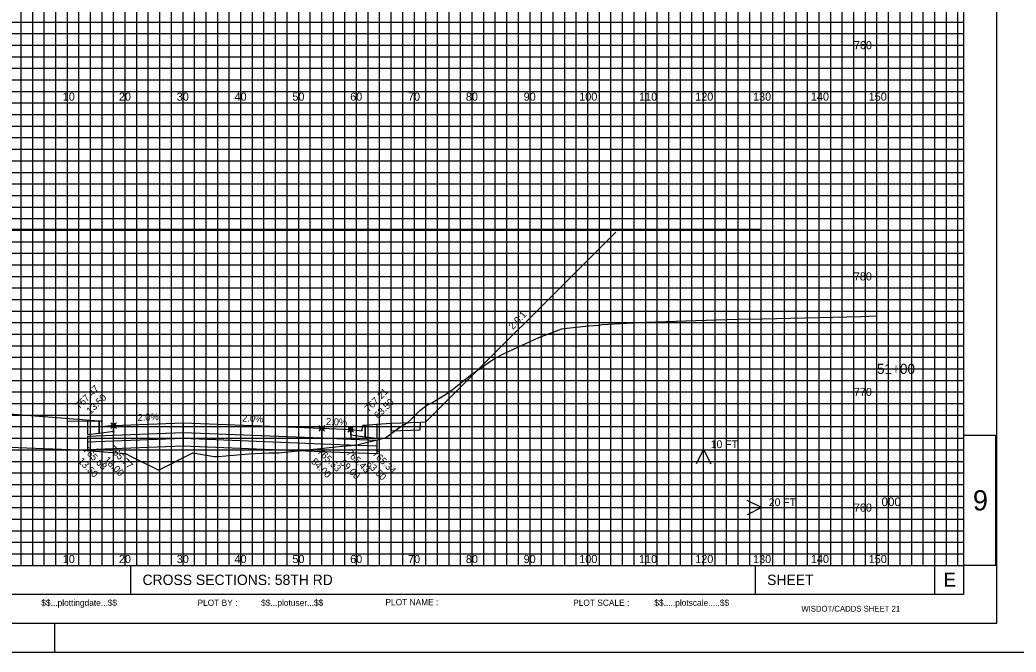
# Model space of a CAD drawing. Extents: x 578243 to 601557, y 174899 to 175559.
# Drawn here: x 601041.6 to 601213.9, y 174898.8 to 175008.2 of the extents above; entities that cross this region are included whole.
import ezdxf

# ---------------------------------------------------------------- set-up
doc = ezdxf.new("R2010")
doc.units = 0
for name, color, linetype in [('E_PROF_Grid', 7, 'Continuous'), ('E_PROF_GridMin', 7, 'Continuous'), ('P_CRDR_Label', 7, 'Continuous'), ('P_CRDR_Link', 7, 'Continuous'), ('P_E_XS_Ground', 7, 'Continuous'), ('P_RW_SlopeIntercepts', 7, 'Continuous'), ('P_XS_Text', 7, 'Continuous'), ('PLT_Sheet_Border', 7, 'Continuous'), ('PLT_Sheet_Info', 7, 'Continuous')]:
    doc.layers.add(name, color=color, linetype=linetype)

msp = doc.modelspace()

# ---------------------------------------------------------------- linework, layer by layer
at = {"layer": 'E_PROF_Grid'}
for p, q in [((601049.84, 174913.8), (601049.84, 175108.8)), ((601059.84, 174913.8), (601059.84, 175108.8)), ((601069.84, 174913.8), (601069.84, 175108.8)), ((601079.84, 174913.8), (601079.84, 175108.8)), ((601089.84, 174913.8), (601089.84, 175108.8)), ((601099.84, 174913.8), (601099.84, 175108.8)), ((601109.84, 174913.8), (601109.84, 175108.8)), ((601119.84, 174913.8), (601119.84, 175108.8)), ((601129.84, 174913.8), (601129.84, 175108.8)), ((601139.84, 174913.8), (601139.84, 175108.8)), ((601149.84, 174913.8), (601149.84, 175108.8)), ((601159.84, 174913.8), (601159.84, 175108.8)), ((601169.84, 174913.8), (601169.84, 175108.8)), ((601179.84, 174913.8), (601179.84, 175108.8)), ((601189.84, 174913.8), (601189.84, 175108.8)), ((601199.84, 174913.8), (601199.84, 175108.8)), ((600889.84, 175003.8), (601204.84, 175003.8)), ((600889.84, 174993.8), (601204.84, 174993.8)), ((600889.84, 174983.8), (601204.84, 174983.8)), ((600889.84, 174973.8), (601204.84, 174973.8)), ((600889.84, 174963.8), (601204.84, 174963.8)), ((600889.84, 174953.8), (601204.84, 174953.8)), ((600889.84, 174943.8), (601204.84, 174943.8)), ((600889.84, 174933.8), (601204.84, 174933.8)), ((600889.84, 174923.8), (601204.84, 174923.8))]:
    msp.add_line(p, q, dxfattribs=at)
at = {"layer": 'E_PROF_GridMin'}
for p, q in [((601041.84, 174913.8), (601041.84, 175108.8)), ((601043.84, 174913.8), (601043.84, 175108.8)), ((601045.84, 174913.8), (601045.84, 175108.8)), ((601047.84, 174913.8), (601047.84, 175108.8)), ((601051.84, 174913.8), (601051.84, 175108.8)), ((601053.84, 174913.8), (601053.84, 175108.8)), ((601055.84, 174913.8), (601055.84, 175108.8)), ((601057.84, 174913.8), (601057.84, 175108.8)), ((601061.84, 174913.8), (601061.84, 175108.8)), ((601063.84, 174913.8), (601063.84, 175108.8)), ((601065.84, 174913.8), (601065.84, 175108.8)), ((601067.84, 174913.8), (601067.84, 175108.8)), ((601071.84, 174913.8), (601071.84, 175108.8)), ((601073.84, 174913.8), (601073.84, 175108.8)), ((601075.84, 174913.8), (601075.84, 175108.8)), ((601077.84, 174913.8), (601077.84, 175108.8)), ((601081.84, 174913.8), (601081.84, 175108.8)), ((601083.84, 174913.8), (601083.84, 175108.8)), ((601085.84, 174913.8), (601085.84, 175108.8)), ((601087.84, 174913.8), (601087.84, 175108.8)), ((601091.84, 174913.8), (601091.84, 175108.8)), ((601093.84, 174913.8), (601093.84, 175108.8)), ((601095.84, 174913.8), (601095.84, 175108.8)), ((601097.84, 174913.8), (601097.84, 175108.8)), ((601101.84, 174913.8), (601101.84, 175108.8)), ((601103.84, 174913.8), (601103.84, 175108.8)), ((601105.84, 174913.8), (601105.84, 175108.8)), ((601107.84, 174913.8), (601107.84, 175108.8)), ((601111.84, 174913.8), (601111.84, 175108.8)), ((601113.84, 174913.8), (601113.84, 175108.8)), ((601115.84, 174913.8), (601115.84, 175108.8)), ((601117.84, 174913.8), (601117.84, 175108.8)), ((601121.84, 174913.8), (601121.84, 175108.8)), ((601123.84, 174913.8), (601123.84, 175108.8)), ((601125.84, 174913.8), (601125.84, 175108.8)), ((601127.84, 174913.8), (601127.84, 175108.8)), ((601131.84, 174913.8), (601131.84, 175108.8)), ((601133.84, 174913.8), (601133.84, 175108.8)), ((601135.84, 174913.8), (601135.84, 175108.8)), ((601137.84, 174913.8), (601137.84, 175108.8)), ((601141.84, 174913.8), (601141.84, 175108.8)), ((601143.84, 174913.8), (601143.84, 175108.8)), ((601145.84, 174913.8), (601145.84, 175108.8)), ((601147.84, 174913.8), (601147.84, 175108.8)), ((601151.84, 174913.8), (601151.84, 175108.8)), ((601153.84, 174913.8), (601153.84, 175108.8)), ((601155.84, 174913.8), (601155.84, 175108.8)), ((601157.84, 174913.8), (601157.84, 175108.8)), ((601161.84, 174913.8), (601161.84, 175108.8)), ((601163.84, 174913.8), (601163.84, 175108.8)), ((601165.84, 174913.8), (601165.84, 175108.8)), ((601167.84, 174913.8), (601167.84, 175108.8)), ((601171.84, 174913.8), (601171.84, 175108.8)), ((601173.84, 174913.8), (601173.84, 175108.8)), ((601175.84, 174913.8), (601175.84, 175108.8)), ((601177.84, 174913.8), (601177.84, 175108.8)), ((601181.84, 174913.8), (601181.84, 175108.8)), ((601183.84, 174913.8), (601183.84, 175108.8)), ((601185.84, 174913.8), (601185.84, 175108.8)), ((601187.84, 174913.8), (601187.84, 175108.8)), ((601191.84, 174913.8), (601191.84, 175108.8)), ((601193.84, 174913.8), (601193.84, 175108.8)), ((601195.84, 174913.8), (601195.84, 175108.8)), ((601197.84, 174913.8), (601197.84, 175108.8)), ((601201.84, 174913.8), (601201.84, 175108.8)), ((601203.84, 174913.8), (601203.84, 175108.8)), ((600889.84, 175007.8), (601204.84, 175007.8)), ((600889.84, 175005.8), (601204.84, 175005.8)), ((600889.84, 175001.8), (601204.84, 175001.8)), ((600889.84, 174999.8), (601204.84, 174999.8)), ((600889.84, 174997.8), (601204.84, 174997.8)), ((600889.84, 174995.8), (601204.84, 174995.8)), ((600889.84, 174991.8), (601204.84, 174991.8)), ((600889.84, 174989.8), (601204.84, 174989.8)), ((600889.84, 174987.8), (601204.84, 174987.8)), ((600889.84, 174985.8), (601204.84, 174985.8)), ((600889.84, 174981.8), (601204.84, 174981.8)), ((600889.84, 174979.8), (601204.84, 174979.8)), ((600889.84, 174977.8), (601204.84, 174977.8)), ((600889.84, 174975.8), (601204.84, 174975.8)), ((600889.84, 174971.8), (601204.84, 174971.8)), ((600889.84, 174969.8), (601204.84, 174969.8)), ((600889.84, 174967.8), (601204.84, 174967.8)), ((600889.84, 174965.8), (601204.84, 174965.8)), ((600889.84, 174961.8), (601204.84, 174961.8)), ((600889.84, 174959.8), (601204.84, 174959.8)), ((600889.84, 174957.8), (601204.84, 174957.8)), ((600889.84, 174955.8), (601204.84, 174955.8)), ((600889.84, 174951.8), (601204.84, 174951.8)), ((600889.84, 174949.8), (601204.84, 174949.8)), ((600889.84, 174947.8), (601204.84, 174947.8)), ((600889.84, 174945.8), (601204.84, 174945.8)), ((600889.84, 174941.8), (601204.84, 174941.8)), ((600889.84, 174939.8), (601204.84, 174939.8)), ((600889.84, 174937.8), (601204.84, 174937.8)), ((600889.84, 174935.8), (601204.84, 174935.8)), ((600889.84, 174931.8), (601204.84, 174931.8)), ((600889.84, 174929.8), (601204.84, 174929.8)), ((600889.84, 174927.8), (601204.84, 174927.8)), ((600889.84, 174925.8), (601204.84, 174925.8)), ((600889.84, 174921.8), (601204.84, 174921.8)), ((600889.84, 174919.8), (601204.84, 174919.8)), ((600889.84, 174917.8), (601204.84, 174917.8)), ((600889.84, 174915.8), (601204.84, 174915.8)), ((601207.19, 174898.8), (601217.19, 174898.8))]:
    msp.add_line(p, q, dxfattribs=at)
at = {"layer": 'P_CRDR_Label'}
for points in [[(601057.34, 174937.5), (601058.33, 174938.49)], [(601057.34, 174938.49), (601058.33, 174937.5)], [(601093.34, 174937.02), (601094.33, 174938.01)], [(601093.34, 174938.01), (601094.33, 174937.02)], [(601098.34, 174936.82), (601099.33, 174937.81)], [(601098.34, 174937.81), (601099.33, 174936.82)]]:
    msp.add_lwpolyline(points, dxfattribs=at)
for centre in [(601057.84, 174938), (601093.84, 174937.52), (601098.84, 174937.32)]:
    msp.add_circle(centre, 0.35, dxfattribs=at)
at = {"layer": 'P_CRDR_Link'}
msp.add_line((601144.69, 174971.46), (601111.84, 174938.61), dxfattribs=at)
for points in [[(601055.34, 174938.75), (601039.84, 174939.99)], [(601055.34, 174938.75), (601039.84, 174939.99)], [(601053.34, 174938.73), (601049.84, 174938.7)], [(601053.34, 174938.73), (601049.84, 174938.7)], [(601055.34, 174938.75), (601053.34, 174938.73)], [(601053.34, 174938.73), (601053.34, 174936.43)], [(601053.34, 174938.73), (601053.34, 174936.43)], [(601053.34, 174938.73), (601053.34, 174936.43)], [(601055.66, 174938.75), (601055.34, 174938.75)], [(601055.66, 174938.75), (601055.34, 174938.75)], [(601055.34, 174938.75), (601055.34, 174936.68)], [(601055.34, 174936.68), (601055.34, 174938.75)], [(601055.74, 174938.7), (601055.66, 174938.75)], [(601055.74, 174938.7), (601055.66, 174938.75)], [(601055.8, 174938.59), (601055.74, 174938.7)], [(601055.8, 174938.59), (601055.74, 174938.7)], [(601055.83, 174938.43), (601055.8, 174938.59)], [(601055.83, 174938.43), (601055.8, 174938.59)], [(601055.84, 174937.75), (601055.83, 174938.43)], [(601055.84, 174937.75), (601055.83, 174938.43)], [(601057.84, 174938), (601069.84, 174938.48)], [(601069.84, 174938.48), (601069.84, 174936.81)], [(601069.84, 174938.48), (601093.84, 174937.52)], [(601069.84, 174938.48), (601069.84, 174936.81)], [(601101.34, 174938.07), (601103.34, 174938.23)], [(601103.34, 174938.23), (601105.84, 174938.43)], [(601103.34, 174938.23), (601105.84, 174938.43)], [(601103.34, 174938.23), (601103.34, 174935.75)], [(601103.34, 174938.23), (601103.34, 174935.75)], [(601103.34, 174938.23), (601103.34, 174935.75)], [(601105.84, 174938.43), (601110.84, 174938.58)], [(601105.84, 174938.43), (601110.84, 174938.58)], [(601105.84, 174938.43), (601105.84, 174937.76)], [(601110.84, 174938.58), (601110.83, 174937.91)], [(601110.84, 174938.58), (601111.84, 174938.61)], [(601110.84, 174938.58), (601111.84, 174938.61)], [(601053.34, 174936.43), (601055.34, 174936.68)], [(601055.34, 174936.68), (601057.84, 174937)], [(601055.34, 174936.68), (601057.84, 174937)], [(601057.84, 174938), (601055.84, 174937.75)], [(601057.84, 174938), (601055.84, 174937.75)], [(601057.84, 174937), (601057.84, 174938)], [(601057.84, 174938), (601057.84, 174936.33)], [(601057.84, 174936.33), (601069.84, 174936.81)], [(601069.84, 174936.81), (601069.84, 174935.81)], [(601069.84, 174936.81), (601093.84, 174935.85)], [(601069.84, 174936.81), (601069.84, 174935.81)], [(601093.84, 174937.52), (601093.84, 174935.85)], [(601093.84, 174937.52), (601098.84, 174937.32)], [(601093.84, 174937.52), (601093.84, 174935.85)], [(601098.84, 174937.32), (601098.84, 174935.65)], [(601098.84, 174937.32), (601100.84, 174937.07)], [(601098.84, 174937.32), (601100.84, 174937.07)], [(601098.84, 174936.32), (601098.84, 174937.32)], [(601100.84, 174937.07), (601100.85, 174937.75)], [(601100.84, 174937.07), (601100.85, 174937.75)], [(601100.85, 174937.75), (601100.88, 174937.91)], [(601100.85, 174937.75), (601100.88, 174937.91)], [(601100.88, 174937.91), (601100.94, 174938.02)], [(601100.88, 174937.91), (601100.94, 174938.02)], [(601100.94, 174938.02), (601101.02, 174938.07)], [(601100.94, 174938.02), (601101.02, 174938.07)], [(601101.02, 174938.07), (601101.34, 174938.07)], [(601101.02, 174938.07), (601101.34, 174938.07)], [(601101.34, 174938.07), (601101.34, 174936)], [(601101.34, 174936), (601101.34, 174938.07)], [(601105.84, 174937.76), (601110.83, 174937.91)], [(601105.84, 174937.76), (601105.85, 174937.1)], [(601105.85, 174937.1), (601110.83, 174937.25)], [(601110.83, 174937.25), (601110.83, 174937.91)], [(601053.34, 174936.15), (601057.84, 174936.33)], [(601053.34, 174936.15), (601053.34, 174935.15)], [(601053.34, 174935.15), (601069.84, 174935.81)], [(601053.34, 174935.15), (601053.34, 174933.82)], [(601069.84, 174935.81), (601069.84, 174934.48)], [(601069.84, 174935.81), (601093.84, 174934.85)], [(601069.84, 174935.81), (601069.84, 174934.48)], [(601093.84, 174935.85), (601093.84, 174934.85)], [(601093.84, 174935.85), (601098.84, 174935.65)], [(601093.84, 174935.85), (601093.84, 174934.85)], [(601093.84, 174934.85), (601093.84, 174933.52)], [(601093.84, 174934.85), (601103.34, 174934.47)], [(601093.84, 174934.85), (601093.84, 174933.52)], [(601101.34, 174936), (601098.84, 174936.32)], [(601101.34, 174936), (601098.84, 174936.32)], [(601098.84, 174935.65), (601103.34, 174935.47)], [(601103.34, 174935.75), (601101.34, 174936)], [(601103.34, 174935.47), (601103.34, 174934.47)], [(601053.34, 174933.82), (601069.84, 174934.48)], [(601069.84, 174934.48), (601093.84, 174933.52)], [(601093.84, 174933.52), (601103.34, 174933.14)], [(601103.34, 174934.47), (601103.34, 174933.14)]]:
    msp.add_lwpolyline(points, dxfattribs=at)
at = {"layer": 'P_E_XS_Ground'}
msp.add_lwpolyline([(601039.84, 174934.26), (601051.84, 174933.78), (601056.9, 174933.37), (601059.9, 174933.13), (601061.19, 174932.48), (601065.54, 174930.31), (601065.58, 174930.3), (601071.52, 174933.27), (601075.2, 174932.62), (601075.89, 174932.61), (601081.24, 174933.12), (601084.67, 174933.26), (601085.88, 174933.3), (601086.42, 174933.29), (601091.83, 174933.83), (601093.64, 174934.03), (601096.19, 174934.32), (601097.42, 174934.42), (601099.69, 174934.58), (601099.91, 174934.63), (601099.91, 174934.63), (601104.81, 174935.85), (601104.84, 174935.86), (601107.33, 174937.74), (601108.78, 174938.59), (601110.78, 174940.59), (601112, 174941.49), (601112.86, 174941.95), (601115.84, 174943.79), (601117.88, 174945.36), (601119.79, 174946.87), (601122.6, 174948.83), (601123.69, 174949.57), (601125.36, 174950.43), (601131.37, 174953.24), (601135.35, 174954.71), (601135.68, 174954.8), (601140.03, 174955.23), (601141.84, 174955.38), (601142.32, 174955.46), (601149.79, 174955.9), (601162.05, 174956.29), (601165.86, 174956.4), (601170.07, 174956.47), (601187.07, 174956.87), (601189.84, 174956.96)], dxfattribs=at)
at = {"layer": 'P_RW_SlopeIntercepts'}
msp.add_line((600933.84, 174971.98), (601169.84, 174971.98), dxfattribs=at)
at = {"layer": 'PLT_Sheet_Border'}
for points in [[(600877.19, 174898.8), (601217.19, 174898.8), (601217.19, 175118.8), (600877.19, 175118.8)], [(600879.59, 174903.8), (601210.59, 174903.8), (601210.59, 175113.8), (600879.59, 175113.8)]]:
    msp.add_lwpolyline(points, close=True, dxfattribs=at)
at = {"layer": 'PLT_Sheet_Info'}
for p, q in [((601204.84, 174908.8), (601204.84, 175108.8)), ((600889.84, 174913.8), (601204.84, 174913.8)), ((601060.84, 174908.8), (601060.84, 174913.8)), ((601168.84, 174908.8), (601168.84, 174913.8)), ((601199.84, 174908.8), (601199.84, 174913.8)), ((600889.84, 174908.8), (601204.84, 174908.8)), ((601047.69, 174898.8), (601047.69, 174903.8)), ((601042.69, 174898.8), (601052.69, 174898.8))]:
    msp.add_line(p, q, dxfattribs=at)
msp.add_lwpolyline([(601204.84, 174936.3), (601210.34, 174936.3), (601210.34, 174913.8), (601204.84, 174913.8)], close=True, dxfattribs=at)
for points in [[(601159.84, 174933.84), (601158.6, 174931.36)], [(601159.84, 174923.8), (601159.84, 174933.84), (601161.08, 174931.36)], [(601169.89, 174923.8), (601167.4, 174925.04)], [(601159.84, 174923.8), (601169.89, 174923.8), (601167.4, 174922.55)]]:
    msp.add_lwpolyline(points, dxfattribs=at)

# ---------------------------------------------------------------- texts
at = {"layer": 'P_CRDR_Label'}
for s, rotation, p in [('2.0:1', 46.711, (601126.88, 174954.52)), ('767.47', 45, (601051.93, 174940.77)), ('13.50', 45, (601053.87, 174939.89)), ('767.21', 45, (601101.93, 174940.27)), ('63.50', 45, (601103.58, 174939.1)), ('2.0%', 2.2906, (601062, 174938.78)), ('2.0%', 357.7094, (601080.05, 174938.69)), ('2.0%', 357.7094, (601094.55, 174938.11)), ('765.68', 315, (601052.49, 174933.67)), ('765.77', 315, (601056.99, 174933.85)), ('765.53', 315, (601092.99, 174933.37)), ('765.43', 315, (601097.99, 174933.17)), ('765.34', 315, (601102.49, 174932.99)), ('13.50', 315, (601051.6, 174931.73)), ('18.00', 315, (601056.08, 174931.94)), ('54.00', 315, (601091.9, 174931.64)), ('59.00', 315, (601096.89, 174931.44)), ('63.50', 315, (601101.43, 174931.23))]:
    msp.add_text(s, height=1.2, rotation=rotation, dxfattribs=at).set_placement(p)
at = {"layer": 'P_XS_Text'}
for s, height, p in [('760', 1.4, (601185.84, 175003.1)), ('10', 1.4, (601049.04, 174994.2)), ('20', 1.4, (601058.75, 174994.2)), ('30', 1.4, (601068.75, 174994.2)), ('40', 1.4, (601078.75, 174994.2)), ('50', 1.4, (601088.75, 174994.2)), ('60', 1.4, (601098.75, 174994.2)), ('70', 1.4, (601108.75, 174994.2)), ('80', 1.4, (601118.75, 174994.2)), ('90', 1.4, (601128.74, 174994.2)), ('100', 1.4, (601138.36, 174994.2)), ('110', 1.4, (601148.7, 174994.2)), ('120', 1.4, (601158.41, 174994.2)), ('130', 1.4, (601168.41, 174994.2)), ('140', 1.4, (601178.41, 174994.2)), ('150', 1.4, (601188.41, 174994.2)), ('780', 1.4, (601185.84, 174963.1)), ('51+00', 1.75, (601189.84, 174946.92)), ('770', 1.4, (601185.84, 174943.1)), ('760', 1.4, (601185.84, 174923.1)), ('10', 1.4, (601049.04, 174914.2)), ('20', 1.4, (601058.75, 174914.2)), ('30', 1.4, (601068.75, 174914.2)), ('40', 1.4, (601078.75, 174914.2)), ('50', 1.4, (601088.75, 174914.2)), ('60', 1.4, (601098.75, 174914.2)), ('70', 1.4, (601108.75, 174914.2)), ('80', 1.4, (601118.75, 174914.2)), ('90', 1.4, (601128.74, 174914.2)), ('100', 1.4, (601138.36, 174914.2)), ('110', 1.4, (601148.7, 174914.2)), ('120', 1.4, (601158.41, 174914.2)), ('130', 1.4, (601168.41, 174914.2)), ('140', 1.4, (601178.41, 174914.2)), ('150', 1.4, (601188.41, 174914.2))]:
    msp.add_text(s, height=height, rotation=360, dxfattribs=at).set_placement(p)
at = {"layer": 'PLT_Sheet_Info'}
for s, height, p in [('  10 FT', 1.347, (601160.09, 174934.09)), ('9', 3.5, (601206.42, 174923.3)), ('  20 FT', 1.347, (601170.14, 174924.05)), ('     000', 1.5, (601187.84, 174924.05)), ('E', 2.4, (601201.36, 174910.12)), ('CROSS SECTIONS: 58TH RD                           ', 1.8, (601062.84, 174910.4)), ('SHEET ', 1.8, (601170.84, 174910.4)), ('PLOT NAME :                      ', 1.08, (601104.84, 174906.9)), ('PLOT SCALE : ', 1.08, (601137.3, 174906.8)), ('$$.....plotscale.....$$', 1.08, (601151.34, 174906.8)), ('WISDOT/CADDS SHEET 21', 1, (601176.76, 174905.8))]:
    msp.add_text(s, height=height, dxfattribs=at).set_placement(p)
for s, p in [('$$...plottingdate...$$', (601045.34, 174906.8)), ('PLOT BY :', (601072.34, 174906.8)), ('$$...plotuser...$$', (601083.34, 174906.8))]:
    msp.add_text(s, height=1.08, rotation=360, dxfattribs=at).set_placement(p)

doc.saveas('drawing.dxf')
